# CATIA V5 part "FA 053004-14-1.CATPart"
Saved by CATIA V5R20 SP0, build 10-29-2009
Part number: FA 053004-14-1
Revision: ANY
Definition: UNKNOWN
Nomenclature: FA 053004-14-1
Source: Unknown
Bounding box of the stored display mesh (mm): x -2.5 to 2.5, y -6.775 to 5.225, z -2.5 to 2.5
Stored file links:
  C:\Users\Utente\Desktop\IO LAVORO\3D X SITO CF\CUMSA\3D files FA\FA 053004-21\FA 053004-14-1.CATPart

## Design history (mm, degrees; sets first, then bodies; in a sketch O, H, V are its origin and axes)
Body1 "Cortar-Extruir3" (main body)
  Solid1: solid without history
